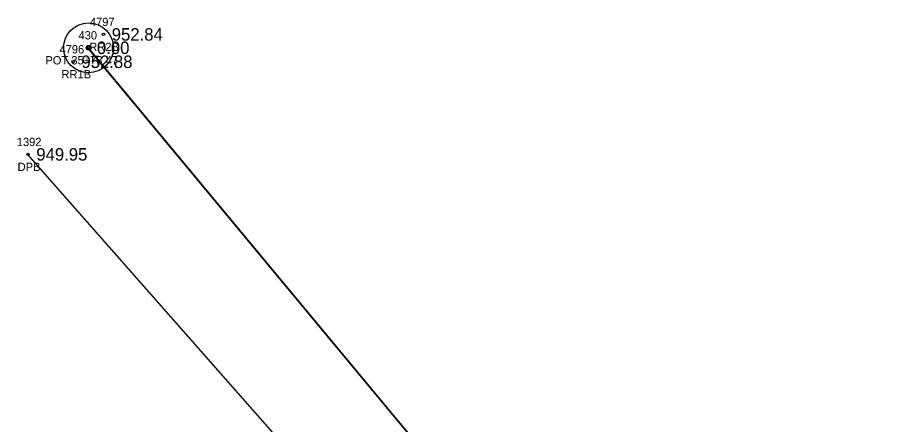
# Model space of a CAD drawing. Extents: x 1575382 to 1578175, y 1099175 to 1101955.
# Drawn here: x 1576248.3 to 1576354.3, y 1099780.7 to 1099829.6 of the extents above; entities that cross this region are included whole.
import ezdxf

# ---------------------------------------------------------------- set-up
doc = ezdxf.new("R2010")
doc.units = 0
for name, color, linetype in [('RD_EX_Driveway', 7, 'Continuous'), ('RD_EX_Driveway_txCode', 7, 'Continuous'), ('RD_EX_RailRoad', 7, 'Continuous'), ('RD_EX_RailRoad_txCode', 7, 'Continuous'), ('RD_EX_TX_Driveway_ELEV', 7, 'Continuous'), ('RD_EX_TX_RailRoad_ELEV', 7, 'Continuous'), ('RD_HC_Cl', 7, 'Continuous'), ('RD_HC_Data', 7, 'Continuous'), ('RD_HC_Survey_ELEV', 7, 'Continuous'), ('RD_HC_txCode', 7, 'Continuous'), ('RD_SMD_Locator', 7, 'Continuous')]:
    doc.layers.add(name, color=color, linetype=linetype)

msp = doc.modelspace()

# ---------------------------------------------------------------- linework, layer by layer
at = {"layer": 'RD_EX_Driveway'}
msp.add_lwpolyline([(1576264.88, 1099750.48), (1576281, 1099777.41), (1576249.51, 1099813.16)], dxfattribs=at)
at = {"layer": 'RD_EX_RailRoad'}
msp.add_lwpolyline([(1576586.78, 1099428.1), (1576554.9, 1099466.71), (1576523.69, 1099504.28), (1576490.27, 1099544.77), (1576459.31, 1099582.09), (1576445.84, 1099598.34), (1576409.99, 1099641.44), (1576367.44, 1099692.66), (1576334.67, 1099732.08), (1576298.68, 1099775.46), (1576256.76, 1099825.95)], dxfattribs=at)
at = {"layer": 'RD_HC_Cl'}
msp.add_line((1576594.9, 1099418.51), (1576256.8, 1099825.98), dxfattribs=at)
at = {"layer": 'RD_HC_Data'}
for radius in [3, 0.282]:
    msp.add_circle((1576256.8, 1099825.98), radius, dxfattribs=at)
at = {"layer": 'RD_SMD_Locator'}
for centre in [(1576258.58, 1099827.59), (1576256.8, 1099825.98), (1576254.94, 1099824.3), (1576249.51, 1099813.16)]:
    msp.add_circle(centre, 0.15, dxfattribs=at)

# ---------------------------------------------------------------- texts
at = {"layer": 'RD_EX_Driveway_txCode'}
for s, p in [('1392', (1576248.16, 1099814.16)), ('DPB', (1576248.26, 1099811.16))]:
    msp.add_text(s, height=1, dxfattribs=at).set_placement(p)
at = {"layer": 'RD_EX_RailRoad_txCode'}
for s, p in [('4797', (1576256.95, 1099828.59)), ('RR2B', (1576256.88, 1099825.59)), ('4796', (1576253.29, 1099825.3)), ('RR1B', (1576253.53, 1099822.3))]:
    msp.add_text(s, height=1, dxfattribs=at).set_placement(p)
at = {"layer": 'RD_EX_TX_Driveway_ELEV'}
msp.add_text('949.95', height=1.5, dxfattribs=at).set_placement((1576250.51, 1099812.41))
at = {"layer": 'RD_EX_TX_RailRoad_ELEV'}
for s, p in [('952.84', (1576259.58, 1099826.84)), ('952.88', (1576255.94, 1099823.55))]:
    msp.add_text(s, height=1.5, dxfattribs=at).set_placement(p)
at = {"layer": 'RD_HC_Survey_ELEV'}
msp.add_text('0.00', height=1.5, dxfattribs=at).set_placement((1576257.8, 1099825.23))
at = {"layer": 'RD_HC_txCode'}
for s, p in [('430', (1576255.58, 1099826.98)), ('POT 35+73.47', (1576251.6, 1099823.98))]:
    msp.add_text(s, height=1, dxfattribs=at).set_placement(p)

doc.saveas('drawing.dxf')
